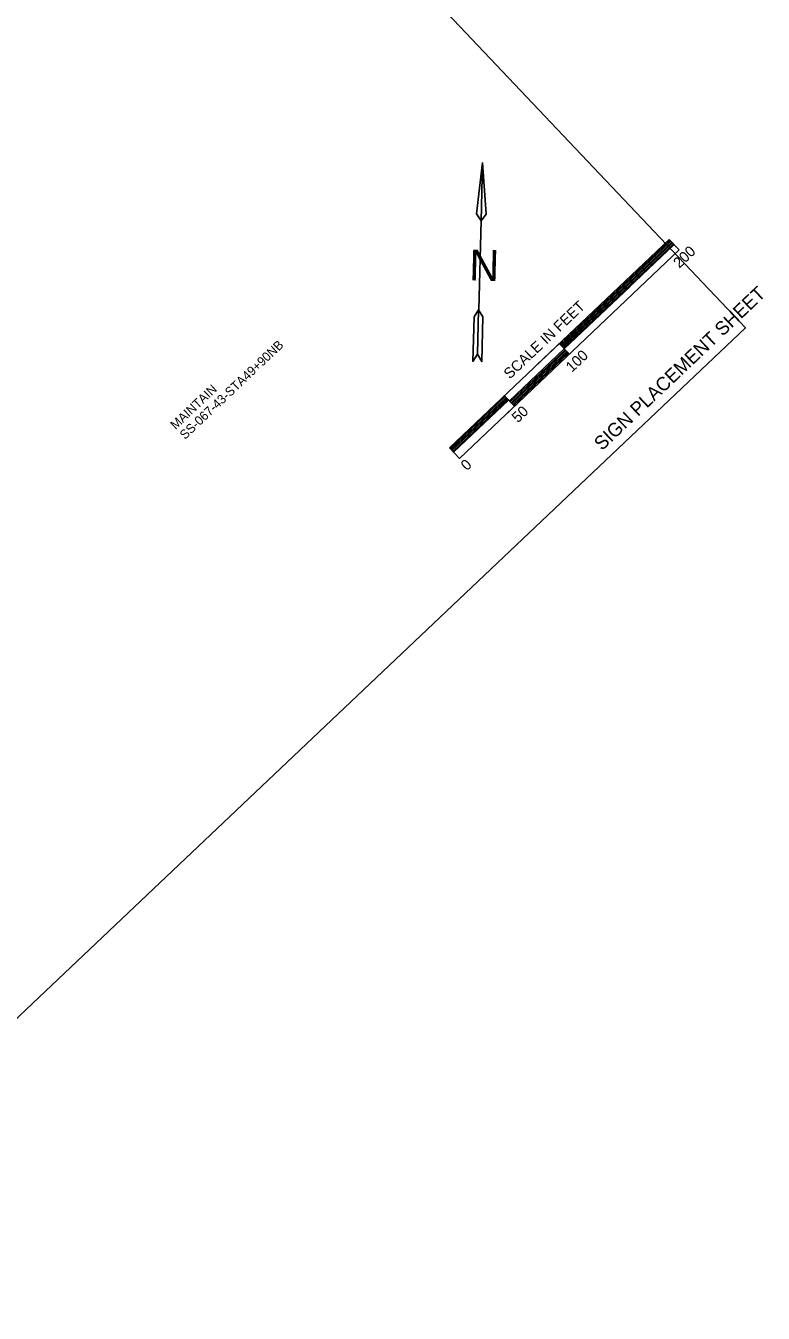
# Model space of a CAD drawing. Extents: x 1289840 to 1295361, y 220865 to 226414.
# Drawn here: x 1292063 to 1292550, y 222059 to 222909 of the extents above; entities that cross this region are included whole.
import ezdxf

# ---------------------------------------------------------------- set-up
doc = ezdxf.new("R2010")
doc.units = 0
for name, color, linetype in [('level 1050', 7, 'Continuous'), ('P_TC_Signs_Permanent', 7, 'Continuous'), ('Plan Text', 7, 'Continuous'), ('R_No Plot', 7, 'Continuous')]:
    doc.layers.add(name, color=color, linetype=linetype)

msp = doc.modelspace()

# ---------------------------------------------------------------- linework, layer by layer
at = {"layer": 'level 1050'}
for p, q in [((1292364.49, 222819.22), (1292360.42, 222785.29)), ((1292360.42, 222785.29), (1292363.45, 222780.71)), ((1292361.88, 222721.89), (1292363.45, 222780.78))]:
    msp.add_line(p, q, dxfattribs=at)
for points in [[(1292364.47, 222819.06), (1292363.45, 222780.71), (1292366.72, 222785.12)], [(1292358.84, 222717.31), (1292358.06, 222687.84), (1292361.08, 222692.62), (1292361.86, 222721.91)], [(1292361.86, 222721.91), (1292364.63, 222717.16), (1292363.85, 222687.69), (1292361.08, 222692.62)]]:
    msp.add_lwpolyline(points, close=True, dxfattribs=at)
at = {"layer": 'Plan Text'}
for p, q in [((1292400.59, 222685.8), (1292487.67, 222768.37)), ((1292415.66, 222698.99), (1292488.22, 222767.79)), ((1292416.21, 222698.4), (1292488.77, 222767.21)), ((1292416.75, 222697.83), (1292489.32, 222766.63)), ((1292417.31, 222697.24), (1292489.87, 222766.05)), ((1292417.86, 222696.66), (1292490.42, 222765.47)), ((1292494.29, 222761.39), (1292487.69, 222768.36)), ((1292349.14, 222623.79), (1292494.27, 222761.41)), ((1292418.41, 222696.08), (1292490.97, 222764.89)), ((1292342.54, 222630.76), (1292458.64, 222740.85)), ((1292418.41, 222696.08), (1292461.95, 222737.36)), ((1292421.72, 222692.59), (1292415.11, 222699.56)), ((1292382.13, 222661.68), (1292418.41, 222696.08)), ((1292382.68, 222661.1), (1292418.96, 222695.5)), ((1292383.23, 222660.52), (1292419.51, 222694.92)), ((1292383.78, 222659.94), (1292420.06, 222694.34)), ((1292384.33, 222659.35), (1292420.61, 222693.76)), ((1292384.88, 222658.78), (1292421.16, 222693.18)), ((1292378.17, 222651.31), (1292407.2, 222678.84)), ((1292343.09, 222630.18), (1292379.37, 222664.58)), ((1292343.64, 222629.6), (1292379.92, 222664)), ((1292344.19, 222629.02), (1292380.47, 222663.42)), ((1292385.43, 222658.19), (1292378.83, 222665.16)), ((1292342.54, 222630.76), (1292371.56, 222658.28)), ((1292344.74, 222628.43), (1292381.03, 222662.84)), ((1292345.29, 222627.86), (1292381.57, 222662.26)), ((1292349.14, 222623.79), (1292342.54, 222630.76))]:
    msp.add_line(p, q, dxfattribs=at)
at = {"layer": 'R_No Plot'}
msp.add_lwpolyline([(1290742.61, 222423.83), (1291831.33, 223455.67), (1292538, 222710.05), (1291449.29, 221678.2)], close=True, dxfattribs=at)

# ---------------------------------------------------------------- texts
at = {"layer": 'level 1050'}
for s, height, rotation, p in [('N', 20.39, 358.47284, (1292355.48, 222741.33)), ('SIGN PLACEMENT SHEET', 9, 43.46361, (1292443.26, 222628.5))]:
    msp.add_text(s, height=height, rotation=rotation, dxfattribs=at).set_placement(p)
at = {"layer": 'P_TC_Signs_Permanent'}
for s, p in [('SS-067-43-STA49+90NB', (1292168.01, 222635.91)), ('MAINTAIN', (1292161.82, 222642.45))]:
    msp.add_text(s, height=6, rotation=43.43866, dxfattribs=at).set_placement(p)
at = {"layer": 'Plan Text'}
for s, height, p in [('200', 7.001, (1292494.34, 222748.95)), ('SCALE IN FEET', 7.0007, (1292382.43, 222675.79)), ('100', 7.001, (1292423.41, 222680.23)), ('50', 7.001, (1292387.75, 222646.89)), ('0', 7, (1292354.11, 222615.25))]:
    msp.add_text(s, height=height, rotation=43.47739, dxfattribs=at).set_placement(p)

doc.saveas('drawing.dxf')
